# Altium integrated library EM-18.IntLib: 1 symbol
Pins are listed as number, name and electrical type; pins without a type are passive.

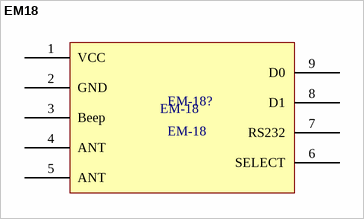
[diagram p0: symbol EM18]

## EM18
designator EM-18?, comment EM-18
Desinator: Bastam Beyrami
footprint EM-18 (Designed by Bastam Beyrami)
pins: 1 VCC, 2 GND, 3 Beep, 4 ANT, 5 ANT, 6 SELECT, 7 RS232, 8 D1, 9 D0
